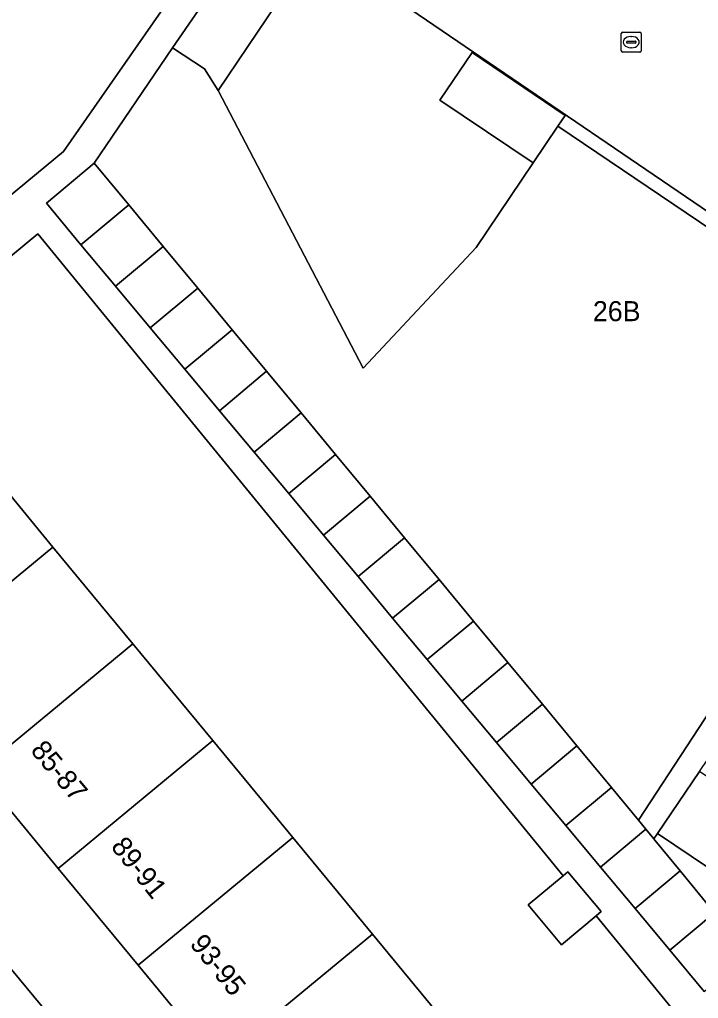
# Model space of a CAD drawing. Extents: x 159279 to 160377, y 384531 to 385888.
# Drawn here: x 159578.55 to 159612.44, y 385021.54 to 385070.37 of the extents above; entities that cross this region are included whole.
import ezdxf

# ---------------------------------------------------------------- set-up
doc = ezdxf.new("R2010")
doc.units = 0
for name, color, linetype in [('IMGEO_Erf', 7, 'Continuous'), ('IMGEO_Pand', 7, 'Continuous'), ('IMGEO_Pand_nummerreeks', 7, 'Continuous'), ('IMGEO_Rioolput', 7, 'Continuous'), ('IMGEO_Voetpad_open', 7, 'Continuous')]:
    doc.layers.add(name, color=color, linetype=linetype)

msp = doc.modelspace()

# ---------------------------------------------------------------- linework, layer by layer
at = {"layer": 'IMGEO_Erf'}
for points in [[(159546.804, 385101.034), (159537.877, 385108.087), (159537.695, 385108.891), (159537.274, 385108.543), (159533.299, 385113.344), (159535.261, 385114.967), (159533.216, 385117.531), (159531.308, 385116.022), (159529.284, 385118.582), (159523.004, 385113.291), (159526.979, 385108.475), (159530.953, 385103.659), (159534.926, 385098.843), (159538.9, 385094.026), (159542.874, 385089.21), (159546.848, 385084.394), (159550.822, 385079.578), (159554.796, 385074.761), (159558.769, 385069.945), (159562.743, 385065.129), (159566.717, 385060.312), (159570.691, 385055.496), (159580.752, 385063.798), (159587.133, 385072.965)], [(159605.427, 385065.055), (159624.013, 385052.496), (159624.349, 385052.994), (159596.098, 385072.248), (159593.354, 385074.105), (159588.461, 385066.829), (159595.71, 385052.989), (159601.338, 385059.003), (159604.187, 385063.22), (159599.538, 385066.362), (159601.141, 385068.735), (159605.791, 385065.594)], [(159588.454, 385018.369), (159584.466, 385023.198), (159580.478, 385028.027), (159576.49, 385032.857), (159572.501, 385037.686), (159568.513, 385042.516), (159564.525, 385047.345), (159560.632, 385044.131), (159597.171, 385000), (159608.541, 384986.268), (159612.383, 384989.392), (159608.395, 384994.221), (159604.407, 384999.051), (159603.623, 385000), (159600.419, 385003.88), (159596.43, 385008.71), (159592.442, 385013.539)]]:
    msp.add_lwpolyline(points, close=True, dxfattribs=at)
for points in [[(159596.098, 385072.248), (159624.349, 385052.994), (159625.544, 385052.18), (159625.595, 385052.256), (159628.137, 385050.539), (159627.997, 385050.332), (159639.81, 385042.315), (159641.888, 385040.935), (159646.054, 385038.17), (159648.699, 385042.808), (159643.519, 385046.2), (159638.742, 385049.328), (159641.057, 385052.874), (159642.257, 385054.712), (159646.683, 385061.425)], [(159616.978, 385013.863), (159607.326, 385025.657), (159605.604, 385024.219), (159603.943, 385026.208), (159605.684, 385027.662), (159579.473, 385059.689), (159572.244, 385053.719), (159576.232, 385048.89), (159580.22, 385044.06), (159584.208, 385039.231), (159588.197, 385034.402), (159592.185, 385029.572), (159596.173, 385024.743), (159600.161, 385019.914), (159604.149, 385015.084), (159608.138, 385010.255), (159612.126, 385005.425), (159612.45, 385005.033)], [(159612.943, 385028.054), (159610.401, 385029.771), (159610.215, 385029.495), (159610.268, 385029.43), (159611.522, 385027.902), (159613.233, 385025.818)]]:
    msp.add_lwpolyline(points, dxfattribs=at)
at = {"layer": 'IMGEO_Pand'}
for points in [[(159593.354, 385074.105), (159593.499, 385074.321), (159591.05, 385076.009), (159586.183, 385068.957), (159587.79, 385067.925), (159588.461, 385066.829)], [(159604.187, 385063.22), (159605.427, 385065.055), (159605.791, 385065.594), (159601.141, 385068.735), (159599.538, 385066.362)], [(159582.271, 385063.219), (159579.892, 385061.211), (159581.62, 385059.141), (159584.002, 385061.13)], [(159584.002, 385061.13), (159581.62, 385059.141), (159583.349, 385057.071), (159585.723, 385059.054)], [(159585.723, 385059.054), (159583.349, 385057.071), (159585.077, 385055.002), (159587.444, 385056.978)], [(159587.444, 385056.978), (159585.077, 385055.002), (159586.805, 385052.932), (159589.165, 385054.902)], [(159589.165, 385054.902), (159586.805, 385052.932), (159588.534, 385050.862), (159590.885, 385052.826)], [(159590.885, 385052.826), (159588.534, 385050.862), (159590.262, 385048.792), (159592.606, 385050.75)], [(159592.606, 385050.75), (159590.262, 385048.792), (159591.99, 385046.723), (159594.327, 385048.674)], [(159572.501, 385037.686), (159580.22, 385044.06), (159576.232, 385048.89), (159568.513, 385042.516)], [(159594.327, 385048.674), (159591.99, 385046.723), (159593.719, 385044.653), (159596.048, 385046.597)], [(159596.048, 385046.597), (159593.719, 385044.653), (159595.447, 385042.583), (159597.768, 385044.521)], [(159597.768, 385044.521), (159595.447, 385042.583), (159597.175, 385040.513), (159599.489, 385042.445)], [(159576.49, 385032.857), (159584.208, 385039.231), (159580.22, 385044.06), (159572.501, 385037.686)], [(159599.489, 385042.445), (159597.175, 385040.513), (159598.904, 385038.444), (159601.21, 385040.369)], [(159601.21, 385040.369), (159598.904, 385038.444), (159600.632, 385036.374), (159602.93, 385038.293)], [(159580.478, 385028.027), (159588.197, 385034.402), (159584.208, 385039.231), (159576.49, 385032.857)], [(159602.93, 385038.293), (159600.632, 385036.374), (159602.36, 385034.304), (159604.651, 385036.217)], [(159604.651, 385036.217), (159602.36, 385034.304), (159604.089, 385032.234), (159606.372, 385034.141)], [(159584.466, 385023.198), (159592.185, 385029.572), (159588.197, 385034.402), (159580.478, 385028.027)], [(159606.372, 385034.141), (159604.089, 385032.234), (159605.817, 385030.165), (159608.093, 385032.065)], [(159615.031, 385031.144), (159612.489, 385032.862), (159610.401, 385029.771), (159612.943, 385028.054)], [(159608.093, 385032.065), (159605.817, 385030.165), (159607.545, 385028.095), (159609.811, 385029.987), (159609.449, 385030.428)], [(159588.454, 385018.369), (159596.173, 385024.743), (159592.185, 385029.572), (159584.466, 385023.198)], [(159610.268, 385029.43), (159610.215, 385029.495), (159609.811, 385029.987), (159607.545, 385028.095), (159609.274, 385026.025), (159611.522, 385027.902)], [(159605.684, 385027.662), (159603.943, 385026.208), (159605.604, 385024.219), (159607.326, 385025.657), (159607.58, 385025.869), (159605.919, 385027.858)], [(159613.233, 385025.818), (159611.522, 385027.902), (159609.274, 385026.025), (159611.002, 385023.955)], [(159614.943, 385023.733), (159613.233, 385025.818), (159611.002, 385023.955), (159612.73, 385021.886)], [(159592.442, 385013.539), (159600.161, 385019.914), (159596.173, 385024.743), (159588.454, 385018.369)]]:
    msp.add_lwpolyline(points, close=True, dxfattribs=at)
msp.add_lwpolyline([(159624.013, 385052.496), (159605.427, 385065.055), (159604.187, 385063.22), (159601.338, 385059.003), (159595.71, 385052.989), (159588.461, 385066.829), (159587.79, 385067.925), (159586.183, 385068.957), (159582.271, 385063.219), (159584.002, 385061.13), (159585.723, 385059.054), (159587.444, 385056.978), (159589.165, 385054.902), (159590.885, 385052.826), (159592.606, 385050.75), (159594.327, 385048.674), (159596.048, 385046.597), (159597.768, 385044.521), (159599.489, 385042.445), (159601.21, 385040.369), (159602.93, 385038.293), (159604.651, 385036.217), (159606.372, 385034.141), (159608.093, 385032.065), (159609.449, 385030.428), (159619.977, 385046.523)], dxfattribs=at)
at = {"layer": 'IMGEO_Rioolput'}
for p, q in [((159608.582, 385068.823), (159608.582, 385069.675)), ((159608.657, 385069.749), (159609.509, 385069.749)), ((159609.583, 385069.675), (159609.583, 385068.823)), ((159608.841, 385069.243), (159608.841, 385069.255)), ((159609.279, 385069.206), (159608.881, 385069.206)), ((159608.884, 385069.292), (159609.282, 385069.292)), ((159609.07, 385069.529), (159609.095, 385069.529)), ((159609.325, 385069.255), (159609.325, 385069.243)), ((159609.509, 385068.749), (159608.657, 385068.749)), ((159609.093, 385068.969), (159609.068, 385068.969))]:
    msp.add_line(p, q, dxfattribs=at)
for points in [[(159608.582, 385068.823), (159608.582, 385069.675)], [(159608.657, 385069.749), (159609.509, 385069.749)], [(159609.583, 385069.675), (159609.583, 385068.823)], [(159609.509, 385068.749), (159608.657, 385068.749)]]:
    msp.add_lwpolyline(points, dxfattribs=at)
for centre, radius, start, end in [((159608.659, 385069.673), 0.0765, 91.552, 178.448), ((159608.659, 385069.673), 0.0765, 91.552, 178.448), ((159609.507, 385069.673), 0.0765, 1.552, 88.448), ((159609.507, 385069.673), 0.0765, 1.552, 88.448), ((159608.881, 385069.252), 0.0403, 85.8775, 175.7526), ((159608.878, 385069.242), 0.0366, 178.938, 274.7102), ((159609.282, 385069.249), 0.043, 264.8664, 352.4533), ((159609.286, 385069.254), 0.0386, 1.7309, 96.639), ((159608.659, 385068.825), 0.0765, 181.552, 268.448), ((159608.659, 385068.825), 0.0765, 181.552, 268.448), ((159609.507, 385068.825), 0.0765, 271.552, 358.448), ((159609.507, 385068.825), 0.0765, 271.552, 358.448)]:
    msp.add_arc(centre, radius, start, end, dxfattribs=at)
for centre, major_axis, ratio, start_param, end_param in [((159609.069, 385069.249), (-0.387, 0.002), 0.722429, 4.712389, 7.853982), ((159609.094, 385069.249), (-0.39, 0.002), 0.717154, 1.570796, 4.712389)]:
    msp.add_ellipse(centre, major_axis=major_axis, ratio=ratio, start_param=start_param, end_param=end_param, dxfattribs=at)
at = {"layer": 'IMGEO_Voetpad_open'}
for points in [[(159597.171, 385000), (159560.632, 385044.131), (159559.124, 385045.952), (159511.318, 385103.692)], [(159612.73, 385021.886), (159611.002, 385023.955), (159609.274, 385026.025), (159607.545, 385028.095), (159605.817, 385030.165), (159604.089, 385032.234), (159602.36, 385034.304), (159600.632, 385036.374), (159598.904, 385038.444), (159597.175, 385040.513), (159595.447, 385042.583), (159593.719, 385044.653), (159591.99, 385046.723), (159590.262, 385048.792), (159588.534, 385050.862), (159586.805, 385052.932), (159585.077, 385055.002), (159583.349, 385057.071), (159581.62, 385059.141), (159579.892, 385061.211), (159582.271, 385063.219), (159586.183, 385068.957), (159591.05, 385076.009)], [(159587.133, 385072.965), (159580.752, 385063.798), (159570.691, 385055.496), (159566.826, 385052.307), (159562.969, 385049.125), (159559.124, 385045.952), (159560.632, 385044.131), (159564.525, 385047.345), (159568.381, 385050.529), (159572.244, 385053.719), (159579.473, 385059.689), (159605.684, 385027.662), (159605.919, 385027.858), (159607.58, 385025.869), (159607.326, 385025.657), (159616.978, 385013.863)]]:
    msp.add_lwpolyline(points, dxfattribs=at)
msp.add_lwpolyline([(159618.029, 385041.059), (159620.103, 385044.129), (159622.352, 385042.61), (159623.667, 385044.476), (159621.381, 385046.02), (159623.506, 385049.164), (159625.544, 385052.18), (159624.349, 385052.994), (159624.013, 385052.496), (159619.977, 385046.523), (159609.449, 385030.428), (159609.811, 385029.987), (159610.215, 385029.495), (159610.401, 385029.771), (159612.489, 385032.862), (159614.608, 385035.996), (159614.694, 385035.938), (159616.078, 385037.901), (159615.952, 385037.986)], close=True, dxfattribs=at)

# ---------------------------------------------------------------- texts
at = {"layer": 'IMGEO_Pand_nummerreeks'}
msp.add_text('26B', height=1, dxfattribs=at).set_placement((159607.168, 385055.328))
for s, rotation, p in [('85-87', 310.0782, (159579.061, 385033.886)), ('89-91', 308.577, (159583.073, 385029.099)), ('93-95', 308.8177, (159587.01, 385024.241))]:
    msp.add_text(s, height=1, rotation=rotation, dxfattribs=at).set_placement(p)

doc.saveas('drawing.dxf')
